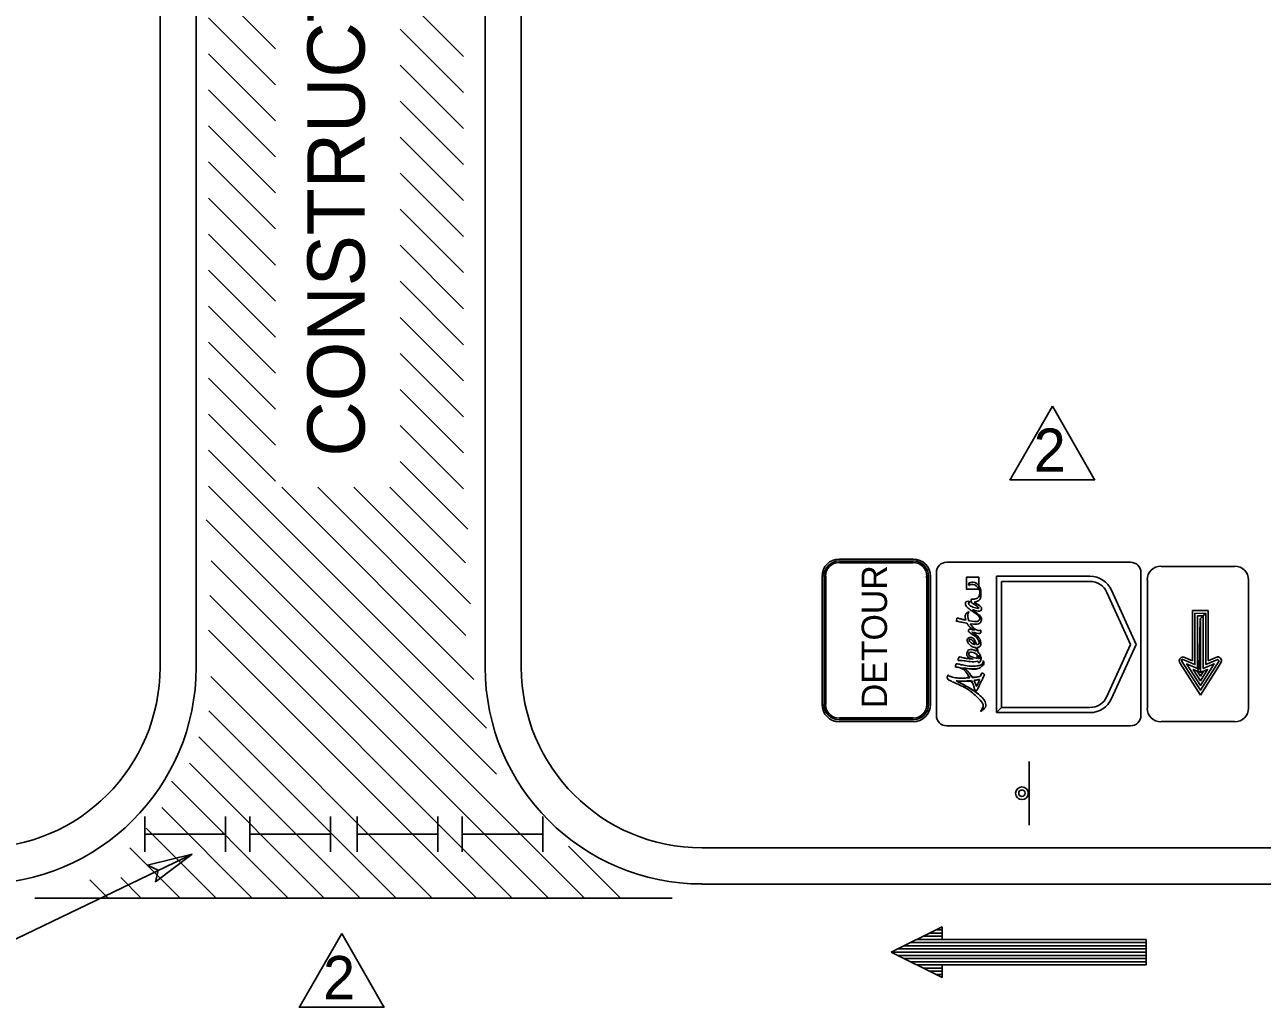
# Model space of a CAD drawing. Extents: x 1806 to 2022, y 110 to 389.
# Drawn here: x 1873.19 to 1914.62, y 221.69 to 254.59 of the extents above; entities that cross this region are included whole.
import ezdxf

# ---------------------------------------------------------------- set-up
doc = ezdxf.new("R2010")
doc.units = 0
for name, color, linetype in [('Level 10', 7, 'Continuous'), ('Level 2', 7, 'Continuous'), ('Level 44', 7, 'Continuous'), ('Level 50', 7, 'Continuous'), ('Level 53', 7, 'Continuous'), ('Level 60', 7, 'Continuous')]:
    doc.layers.add(name, color=color, linetype=linetype)

msp = doc.modelspace()

# ---------------------------------------------------------------- linework, layer by layer
at = {"layer": 'Level 10'}
for p, q in [((1877.715, 272.1), (1877.715, 233.074)), ((1878.925, 233.074), (1878.925, 272.1)), ((1888.603, 233.074), (1888.603, 272.1)), ((1889.812, 233.074), (1889.812, 272.1)), ((1879.343, 256.031), (1881.587, 253.786)), ((1885.752, 255.655), (1887.876, 253.531)), ((1879.343, 254.824), (1881.587, 252.58)), ((1885.752, 254.449), (1887.876, 252.325)), ((1879.343, 253.617), (1881.587, 251.373)), ((1885.752, 253.242), (1887.876, 251.118)), ((1879.343, 252.411), (1881.587, 250.167)), ((1885.752, 252.036), (1887.876, 249.912)), ((1879.343, 251.203), (1881.587, 248.959)), ((1885.752, 250.828), (1887.876, 248.704)), ((1879.343, 249.997), (1881.587, 247.753)), ((1885.752, 249.621), (1887.876, 247.498)), ((1879.343, 248.79), (1881.587, 246.546)), ((1885.752, 248.415), (1887.876, 246.291)), ((1879.343, 247.584), (1881.587, 245.339)), ((1885.752, 247.208), (1887.876, 245.084)), ((1879.343, 246.377), (1881.587, 244.133)), ((1885.752, 246.002), (1887.876, 243.878)), ((1879.343, 245.17), (1881.587, 242.925)), ((1885.752, 244.794), (1887.876, 242.67)), ((1879.343, 243.963), (1881.587, 241.719)), ((1885.752, 243.588), (1887.876, 241.464)), ((1879.343, 242.757), (1881.587, 240.512)), ((1885.752, 242.381), (1887.876, 240.257)), ((1879.343, 241.55), (1881.587, 239.306)), ((1885.752, 241.175), (1887.876, 239.051)), ((1879.343, 240.343), (1888.649, 231.035)), ((1885.752, 239.968), (1888.025, 237.695)), ((1879.343, 239.136), (1888.982, 229.496)), ((1881.791, 239.102), (1888.224, 232.668)), ((1882.997, 239.102), (1887.958, 234.142)), ((1884.204, 239.102), (1888.109, 235.196)), ((1885.41, 239.102), (1887.943, 236.568)), ((1879.255, 238.016), (1891.928, 225.345)), ((1879.426, 236.639), (1890.718, 225.345)), ((1879.38, 235.478), (1889.511, 225.345)), ((1879.338, 234.314), (1888.306, 225.345)), ((1879.413, 232.763), (1886.831, 225.345)), ((1879.35, 231.618), (1885.623, 225.345)), ((1879.019, 230.742), (1884.417, 225.345)), ((1878.697, 229.859), (1883.211, 225.345)), ((1878.095, 229.256), (1882.005, 225.345)), ((1877.771, 228.372), (1880.799, 225.345)), ((1877.203, 226.893), (1877.203, 228.072)), ((1879.903, 226.893), (1879.903, 228.072)), ((1880.726, 226.893), (1880.726, 228.072)), ((1883.426, 226.893), (1883.426, 228.072)), ((1884.314, 226.893), (1884.314, 228.072)), ((1887.014, 226.893), (1887.014, 228.072)), ((1887.837, 226.893), (1887.837, 228.072)), ((1890.537, 226.893), (1890.537, 228.072)), ((1877.203, 227.479), (1879.903, 227.479)), ((1877.253, 227.685), (1879.593, 225.345)), ((1880.726, 227.479), (1883.426, 227.479)), ((1884.314, 227.479), (1887.014, 227.479)), ((1887.837, 227.479), (1890.537, 227.479)), ((1891.392, 227.086), (1893.133, 225.345)), ((1872.333, 223.715), (1878.786, 226.819)), ((1876.706, 227.026), (1878.387, 225.345)), ((1957.331, 227.026), (1895.86, 227.026)), ((1875.361, 225.959), (1875.975, 225.345)), ((1876.404, 226.028), (1877.087, 225.345)), ((1957.331, 225.815), (1895.86, 225.815)), ((1873.528, 225.345), (1894.86, 225.345))]:
    msp.add_line(p, q, dxfattribs=at)
msp.add_lwpolyline([(1878.786, 226.819), (1877.569, 225.889), (1877.658, 226.276), (1877.3, 226.448)], close=True, dxfattribs=at)
for centre, radius, start, end in [((1871.667, 233.074), 6.048, 270, 360), ((1871.667, 233.074), 7.258, 270, 360), ((1895.86, 233.074), 7.258, 180, 270), ((1895.86, 233.074), 6.048, 180, 270)]:
    msp.add_arc(centre, radius, start, end, dxfattribs=at)
at = {"layer": 'Level 2'}
for p, q in [((1904.056, 236.592), (1910.211, 236.592)), ((1903.709, 231.46), (1903.709, 236.245)), ((1903.709, 231.46), (1903.709, 236.245)), ((1910.558, 231.46), (1910.558, 236.245)), ((1905.722, 231.556), (1905.722, 236.121)), ((1905.722, 236.121), (1908.849, 236.121)), ((1908.849, 235.95), (1905.893, 235.95)), ((1905.893, 235.95), (1905.893, 231.727)), ((1910.213, 233.839), (1909.42, 235.582)), ((1909.576, 235.653), (1910.402, 233.839)), ((1909.42, 232.095), (1910.213, 233.839)), ((1910.402, 233.839), (1909.576, 232.024)), ((1905.722, 231.556), (1905.893, 231.727)), ((1905.893, 231.727), (1905.722, 231.556)), ((1905.893, 231.727), (1908.849, 231.727)), ((1908.849, 231.556), (1905.722, 231.556)), ((1904.056, 231.113), (1910.211, 231.113))]:
    msp.add_line(p, q, dxfattribs=at)
for centre, radius, start, end in [((1904.056, 236.245), 0.347, 90, 180), ((1910.211, 236.245), 0.347, 360, 90), ((1908.849, 235.322), 0.799, 24.4568, 90), ((1908.849, 235.322), 0.628, 24.4568, 90), ((1908.849, 232.355), 0.628, 270, 335.5432), ((1908.849, 232.355), 0.799, 270, 335.5432), ((1904.056, 231.46), 0.347, 180, 270), ((1910.211, 231.46), 0.347, 270, 360)]:
    msp.add_arc(centre, radius, start, end, dxfattribs=at)
at = {"layer": 'Level 44'}
for p, q in [((1900.462, 236.694), (1902.927, 236.694)), ((1900.462, 236.629), (1902.927, 236.629)), ((1900.462, 236.575), (1902.927, 236.575)), ((1900.462, 236.575), (1902.927, 236.575)), ((1900.462, 236.575), (1902.927, 236.575)), ((1911.23, 236.452), (1913.695, 236.452)), ((1899.887, 231.832), (1899.887, 236.123)), ((1899.952, 231.832), (1899.952, 236.123)), ((1900.006, 231.832), (1900.006, 236.123)), ((1900.006, 231.832), (1900.006, 236.123)), ((1900.006, 231.832), (1900.006, 236.123)), ((1903.286, 236.066), (1903.284, 236.07)), ((1903.344, 236.095), (1903.342, 236.099)), ((1903.39, 236.123), (1903.39, 231.832)), ((1903.39, 236.123), (1903.39, 231.832)), ((1903.39, 236.123), (1903.39, 231.832)), ((1903.392, 236.119), (1903.39, 236.123)), ((1903.444, 236.123), (1903.444, 231.832)), ((1903.509, 236.123), (1903.509, 231.832)), ((1910.773, 231.709), (1910.773, 236)), ((1914.16, 236), (1914.16, 231.709)), ((1912.281, 233.293), (1912.281, 234.97)), ((1912.281, 234.97), (1912.814, 234.97)), ((1912.814, 234.97), (1912.814, 233.297)), ((1903.396, 234.198), (1903.396, 234.198)), ((1903.396, 234.198), (1903.396, 234.198)), ((1903.396, 234.198), (1903.396, 234.198)), ((1911.974, 233.421), (1912.281, 233.293)), ((1912.814, 233.293), (1913.122, 233.425)), ((1912.55, 232.145), (1911.863, 233.22)), ((1913.233, 233.22), (1912.55, 232.145)), ((1902.927, 231.376), (1900.462, 231.376)), ((1902.927, 231.376), (1900.462, 231.376)), ((1902.927, 231.376), (1900.462, 231.376)), ((1902.927, 231.322), (1900.462, 231.322)), ((1902.927, 231.257), (1900.462, 231.257)), ((1913.695, 231.253), (1911.23, 231.253)), ((1906.812, 227.784), (1906.812, 229.917))]:
    msp.add_line(p, q, dxfattribs=at)
for points in [[(1912.733, 234.88), (1912.733, 233.165), (1913.13, 233.335), (1913.173, 233.289), (1912.55, 232.303), (1911.918, 233.293), (1911.944, 233.34), (1912.366, 233.165), (1912.366, 234.884), (1912.733, 234.88), (1912.644, 234.799), (1912.644, 233.037), (1913.011, 233.186), (1912.55, 232.465), (1912.089, 233.186), (1912.456, 233.037), (1912.456, 234.799), (1912.644, 234.799), (1912.558, 234.709), (1912.558, 232.896), (1912.789, 232.994), (1912.55, 232.623), (1912.307, 233.003), (1912.443, 232.947), (1912.55, 232.777), (1912.657, 232.939), (1912.546, 232.905), (1912.443, 232.947), (1912.503, 233.033), (1912.546, 234.705), (1912.558, 234.709)], [(1912.733, 234.88), (1912.733, 233.165)], [(1914.164, 232.503), (1914.164, 232.575)]]:
    msp.add_lwpolyline(points, dxfattribs=at)
for radius in [0.213, 0.107]:
    msp.add_circle((1906.573, 228.855), radius, dxfattribs=at)
for centre, radius, start, end in [((1900.461, 236.119), 0.581, 90, 180), ((1900.461, 236.119), 0.516, 90, 180), ((1902.931, 236.119), 0.581, 0, 90), ((1902.931, 236.119), 0.516, 0, 90), ((1900.461, 236.119), 0.462, 90, 180), ((1900.461, 236.119), 0.462, 90, 180), ((1900.461, 236.119), 0.462, 90, 180), ((1902.931, 236.119), 0.462, 0, 90), ((1902.931, 236.119), 0.462, 0, 90), ((1902.931, 236.119), 0.462, 0, 90), ((1911.229, 235.996), 0.462, 90, 180), ((1913.698, 235.996), 0.462, 0, 90), ((1911.974, 233.289), 0.132, 90.1051, 212.4986), ((1913.123, 233.291), 0.132, 327.5038, 90.1058), ((1900.461, 231.832), 0.581, 180, 270), ((1900.461, 231.832), 0.516, 180, 270), ((1900.461, 231.832), 0.462, 180, 270), ((1900.461, 231.832), 0.462, 180, 270), ((1900.461, 231.832), 0.462, 180, 270), ((1902.931, 231.832), 0.462, 270, 360), ((1902.931, 231.832), 0.462, 270, 360), ((1902.931, 231.832), 0.581, 270, 360), ((1902.931, 231.832), 0.516, 270, 360), ((1902.931, 231.832), 0.462, 270, 360), ((1911.229, 231.709), 0.462, 180, 270), ((1913.698, 231.709), 0.462, 270, 360)]:
    msp.add_arc(centre, radius, start, end, dxfattribs=at)
at = {"layer": 'Level 50'}
for p, q in [((1902.196, 223.533), (1903.902, 224.386)), ((1903.476, 224.173), (1903.902, 224.173)), ((1903.689, 224.28), (1903.902, 224.28)), ((1903.902, 223.96), (1903.902, 224.386)), ((1902.623, 223.746), (1910.729, 223.746)), ((1902.836, 223.853), (1910.729, 223.853)), ((1903.049, 223.96), (1910.729, 223.96)), ((1903.263, 224.066), (1903.902, 224.066)), ((1903.902, 223.96), (1910.729, 223.96)), ((1910.729, 223.106), (1910.729, 223.96)), ((1902.196, 223.533), (1910.729, 223.533)), ((1902.196, 223.533), (1903.902, 222.68)), ((1902.409, 223.64), (1910.729, 223.64)), ((1902.409, 223.426), (1910.729, 223.426)), ((1902.623, 223.32), (1910.729, 223.32)), ((1902.836, 223.213), (1910.729, 223.213)), ((1903.049, 223.106), (1910.729, 223.106)), ((1903.263, 223), (1903.902, 223)), ((1903.902, 223.106), (1910.729, 223.106)), ((1903.902, 222.68), (1903.902, 223.106)), ((1903.476, 222.893), (1903.902, 222.893)), ((1903.689, 222.786), (1903.902, 222.786))]:
    msp.add_line(p, q, dxfattribs=at)
at = {"layer": 'Level 53'}
msp.add_line((1905.126, 235.801), (1905.126, 235.701), dxfattribs=at)
msp.add_lwpolyline([(1905.126, 235.801), (1905.126, 236.096), (1904.719, 236.096), (1904.719, 235.689), (1905.126, 235.689), (1905.126, 235.701)], dxfattribs=at)
for points, degree in [([(1904.719, 235.689), (1904.719, 235.689), (1905.126, 235.689), (1905.126, 235.689), (1905.126, 235.689), (1905.126, 235.701), (1905.126, 235.701), (1905.073, 235.789), (1904.972, 235.849), (1904.889, 235.849), (1904.817, 235.849), (1904.821, 235.81), (1904.81, 235.815), (1904.782, 235.827), (1904.798, 235.917), (1904.9, 235.922), (1904.986, 235.927), (1905.069, 235.882), (1905.126, 235.801), (1905.126, 235.801), (1905.126, 236.096), (1905.126, 236.096), (1905.126, 236.096), (1904.719, 236.096), (1904.719, 236.096), (1904.719, 236.096), (1904.719, 235.689), (1904.719, 235.689)], 3), ([(1905.126, 235.701), (1905.073, 235.789), (1904.972, 235.849), (1904.889, 235.849), (1904.817, 235.849), (1904.821, 235.81), (1904.81, 235.815), (1904.782, 235.827), (1904.798, 235.917), (1904.9, 235.922), (1904.986, 235.927), (1905.069, 235.882), (1905.126, 235.801)], 3), ([(1904.971, 235.258), (1905.055, 235.268), (1905.2, 235.324), (1905.2, 235.55), (1905.2, 235.651), (1905.172, 235.737), (1905.126, 235.801)], 3), ([(1905.162, 235.575), (1905.162, 235.408), (1905.032, 235.365), (1904.968, 235.357), (1904.925, 235.351), (1904.863, 235.36), (1904.872, 235.287), (1904.878, 235.235), (1904.978, 235.188), (1905.063, 235.123), (1905.136, 235.066), (1905.129, 235.041), (1905.066, 235.054), (1904.988, 235.071), (1904.804, 235.136), (1904.791, 235.211), (1904.785, 235.245), (1904.846, 235.257), (1904.808, 235.273), (1904.77, 235.289), (1904.687, 235.275), (1904.687, 235.197), (1904.687, 235.143), (1904.745, 235.078), (1904.81, 235.025), (1904.867, 234.979), (1905.213, 234.744), (1905.138, 234.645), (1905.103, 234.599), (1904.961, 234.603), (1904.794, 234.632)], 3), ([(1905.126, 235.701), (1905.149, 235.663), (1905.162, 235.621), (1905.162, 235.575)], 2), ([(1904.846, 234.53), (1905.004, 234.512), (1905.145, 234.518), (1905.19, 234.59), (1905.272, 234.722), (1905.055, 234.909), (1904.922, 235.011)], 3), ([(1904.922, 235.011), (1905.04, 234.959), (1905.191, 234.929), (1905.214, 235.008), (1905.241, 235.1), (1905.089, 235.173), (1904.971, 235.258)], 3), ([(1904.693, 234.652), (1904.639, 234.664), (1904.583, 234.677), (1904.53, 234.692), (1904.481, 234.706), (1904.395, 234.747), (1904.379, 234.641), (1904.374, 234.608), (1904.39, 234.622), (1904.435, 234.611), (1904.519, 234.591), (1904.627, 234.565), (1904.736, 234.546)], 3), ([(1904.794, 234.632), (1904.749, 234.749), (1904.764, 234.846), (1904.79, 234.901), (1904.803, 234.928), (1904.801, 234.932), (1904.771, 234.92), (1904.727, 234.903), (1904.659, 234.809), (1904.69, 234.662), (1904.691, 234.659), (1904.692, 234.655), (1904.693, 234.652)], 3), ([(1904.736, 234.546), (1904.786, 234.46), (1904.869, 234.379), (1904.979, 234.32)], 2), ([(1904.898, 234.245), (1904.996, 234.236), (1905.21, 234.172), (1905.199, 234.281), (1905.195, 234.323), (1905.188, 234.305), (1905.151, 234.307), (1905.022, 234.317), (1904.913, 234.424), (1904.846, 234.53)], 3), ([(1904.979, 234.32), (1904.928, 234.33), (1904.872, 234.346), (1904.835, 234.347), (1904.795, 234.349), (1904.786, 234.321), (1904.783, 234.311), (1904.776, 234.288), (1904.788, 234.26), (1904.827, 234.232), (1904.918, 234.168), (1905.061, 234.086), (1905.122, 233.962), (1905.165, 233.873), (1905.121, 233.834), (1905.054, 233.832)], 3), ([(1905.077, 233.737), (1905.149, 233.746), (1905.204, 233.793), (1905.194, 233.901), (1905.179, 234.056), (1904.99, 234.193), (1904.898, 234.245)], 3), ([(1905.054, 233.832), (1905.049, 233.849), (1905.043, 233.865), (1905.037, 233.878), (1904.966, 234.04), (1904.858, 234.095), (1904.793, 234.054), (1904.73, 234.015), (1904.749, 233.904), (1904.842, 233.816), (1904.887, 233.773), (1904.966, 233.74), (1905.037, 233.736)], 3), ([(1904.85, 233.918), (1904.8, 233.972), (1904.803, 233.999), (1904.817, 234.006), (1904.846, 234.021), (1904.949, 233.958), (1905.005, 233.836)], 3), ([(1905.005, 233.836), (1904.95, 233.846), (1904.889, 233.875), (1904.85, 233.918)], 2), ([(1905.037, 233.736), (1905.045, 233.698), (1905.052, 233.656), (1905.058, 233.608)], 2), ([(1905.103, 233.575), (1905.096, 233.629), (1905.088, 233.685), (1905.077, 233.737)], 2), ([(1905.274, 233.247), (1905.268, 233.204), (1905.208, 233.146), (1905.11, 233.129), (1904.933, 233.097), (1904.759, 233.116), (1904.5, 233.168), (1904.451, 233.178), (1904.365, 233.211), (1904.349, 233.105), (1904.344, 233.071), (1904.361, 233.088), (1904.405, 233.079), (1904.599, 233.038), (1904.738, 232.88), (1904.831, 232.721), (1904.61, 232.704), (1904.364, 232.711), (1904.214, 232.753), (1904.087, 232.788), (1904.11, 232.83), (1904.083, 232.778), (1904.055, 232.723), (1904.092, 232.665), (1904.187, 232.617), (1904.282, 232.57), (1904.796, 232.351), (1905.143, 232.002), (1905.321, 231.824), (1905.229, 231.662), (1905.202, 231.63), (1905.18, 231.603), (1905.214, 231.594), (1905.249, 231.626), (1905.405, 231.771), (1905.316, 231.982), (1905.239, 232.059), (1905.026, 232.271), (1904.569, 232.518), (1904.375, 232.618), (1904.485, 232.609), (1904.668, 232.606), (1904.882, 232.626), (1904.935, 232.518), (1904.966, 232.421), (1904.978, 232.375), (1904.991, 232.326), (1905.011, 232.295), (1905.034, 232.294), (1905.059, 232.293), (1905.08, 232.326), (1905.103, 232.374), (1905.144, 232.46), (1905.262, 232.711), (1905.298, 232.772), (1905.329, 232.825), (1905.305, 232.851), (1905.272, 232.867), (1905.229, 232.887), (1905.204, 232.831), (1905.187, 232.777), (1905.115, 232.756), (1905.017, 232.739), (1904.909, 232.728), (1904.831, 232.855), (1904.726, 232.981), (1904.596, 233.053), (1904.705, 233.035), (1905.076, 232.988), (1905.233, 233.105), (1905.267, 233.131), (1905.305, 233.188), (1905.299, 233.243), (1905.297, 233.27), (1905.28, 233.283), (1905.274, 233.28), (1905.269, 233.278), (1905.276, 233.263), (1905.274, 233.247)], 3), ([(1904.938, 233.345), (1904.834, 233.354), (1904.707, 233.37), (1904.59, 233.394), (1904.541, 233.404), (1904.456, 233.437), (1904.439, 233.331), (1904.434, 233.297), (1904.45, 233.302), (1904.496, 233.305), (1904.557, 233.309), (1904.93, 233.24), (1905.093, 233.276)], 3), ([(1904.596, 233.053), (1904.705, 233.035), (1905.076, 232.988), (1905.233, 233.105), (1905.267, 233.131), (1905.305, 233.188), (1905.299, 233.243), (1905.297, 233.27), (1905.28, 233.283), (1905.274, 233.28), (1905.269, 233.278), (1905.276, 233.263), (1905.274, 233.247)], 3), ([(1905.058, 233.608), (1904.936, 233.684), (1904.769, 233.677), (1904.742, 233.566), (1904.709, 233.438), (1904.834, 233.373), (1904.938, 233.345)], 3), ([(1905.082, 233.373), (1904.951, 233.39), (1904.77, 233.458), (1904.799, 233.543), (1904.816, 233.592), (1904.969, 233.566), (1905.071, 233.503)], 3), ([(1905.071, 233.503), (1905.075, 233.462), (1905.079, 233.419), (1905.082, 233.373)], 2), ([(1905.093, 233.276), (1905.108, 233.23), (1905.143, 233.211), (1905.179, 233.27), (1905.204, 233.311), (1905.213, 233.401), (1905.168, 233.491), (1905.152, 233.523), (1905.13, 233.551), (1905.103, 233.575)], 3), ([(1905.123, 233.369), (1905.122, 233.392), (1905.119, 233.428), (1905.115, 233.471)], 2), ([(1905.115, 233.471), (1905.139, 233.448), (1905.157, 233.423), (1905.161, 233.396)], 2), ([(1905.161, 233.359), (1905.156, 233.365), (1905.149, 233.368), (1905.14, 233.368), (1905.134, 233.368), (1905.129, 233.369), (1905.123, 233.369)], 3), ([(1905.161, 233.396), (1905.163, 233.381), (1905.163, 233.369), (1905.161, 233.359)], 2), ([(1905.274, 233.247), (1905.268, 233.204), (1905.208, 233.146), (1905.11, 233.129), (1904.933, 233.097), (1904.759, 233.116), (1904.5, 233.168), (1904.451, 233.178), (1904.365, 233.211), (1904.349, 233.105), (1904.344, 233.071), (1904.361, 233.088), (1904.405, 233.079), (1904.599, 233.038), (1904.738, 232.88), (1904.831, 232.721)], 3), ([(1904.909, 232.728), (1904.831, 232.855), (1904.726, 232.981), (1904.596, 233.053)], 2), ([(1904.882, 232.626), (1904.935, 232.518), (1904.966, 232.421), (1904.978, 232.375), (1904.991, 232.326), (1905.011, 232.295), (1905.034, 232.294), (1905.059, 232.293), (1905.08, 232.326), (1905.103, 232.374), (1905.144, 232.46), (1905.262, 232.711), (1905.298, 232.772), (1905.329, 232.825), (1905.305, 232.851), (1905.272, 232.867), (1905.229, 232.887), (1905.204, 232.831), (1905.187, 232.777)], 3), ([(1904.831, 232.721), (1904.61, 232.704), (1904.364, 232.711), (1904.214, 232.753), (1904.087, 232.788), (1904.11, 232.83), (1904.083, 232.778), (1904.055, 232.723), (1904.092, 232.665), (1904.187, 232.617), (1904.282, 232.57), (1904.796, 232.351), (1905.143, 232.002), (1905.321, 231.824), (1905.229, 231.662), (1905.202, 231.63), (1905.18, 231.603), (1905.214, 231.594), (1905.249, 231.626), (1905.405, 231.771), (1905.316, 231.982), (1905.239, 232.059), (1905.026, 232.271), (1904.569, 232.518), (1904.375, 232.618)], 3), ([(1904.375, 232.618), (1904.485, 232.609), (1904.668, 232.606), (1904.882, 232.626)], 2), ([(1905.187, 232.777), (1905.115, 232.756), (1905.017, 232.739), (1904.909, 232.728)], 2), ([(1904.962, 232.634), (1905.049, 232.645), (1905.111, 232.656), (1905.158, 232.668)], 2), ([(1905.053, 232.43), (1905.032, 232.487), (1905.002, 232.559), (1904.962, 232.634)], 2), ([(1905.053, 232.43), (1905.032, 232.487), (1905.002, 232.559), (1904.962, 232.634), (1905.049, 232.645), (1905.111, 232.656), (1905.158, 232.668), (1905.137, 232.613), (1905.105, 232.534), (1905.053, 232.43)], 3), ([(1905.158, 232.668), (1905.137, 232.613), (1905.105, 232.534), (1905.053, 232.43)], 2)]:
    msp.add_open_spline(points, degree=degree, dxfattribs=at)
at = {"layer": 'Level 60'}
for points in [[(1907.592, 241.823), (1906.199, 239.398)], [(1908.986, 239.398), (1907.592, 241.823)], [(1906.199, 239.398), (1906.173, 239.353), (1909.012, 239.353), (1908.986, 239.398)], [(1883.798, 224.157), (1882.405, 221.732)], [(1885.192, 221.732), (1883.798, 224.157)], [(1882.405, 221.732), (1882.379, 221.687), (1885.218, 221.687), (1885.192, 221.732)]]:
    msp.add_lwpolyline(points, dxfattribs=at)

# ---------------------------------------------------------------- texts
at = {"layer": 'Level 44'}
msp.add_text('DETOUR', height=0.848, rotation=90, dxfattribs=at).set_placement((1902.056, 231.703))
at = {"layer": 'Level 50'}
msp.add_text('CONSTRUCTION ZONE', height=1.92, rotation=90, dxfattribs=at).set_placement((1884.568, 240.126))
at = {"layer": 'Level 60'}
for p in [(1906.965, 239.622), (1883.171, 221.956)]:
    msp.add_text('2', height=1.448, rotation=360, dxfattribs=at).set_placement(p)

doc.saveas('drawing.dxf')
